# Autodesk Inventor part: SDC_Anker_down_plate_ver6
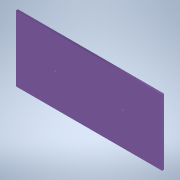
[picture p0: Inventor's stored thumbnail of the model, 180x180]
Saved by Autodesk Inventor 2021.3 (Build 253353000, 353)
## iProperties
Created: 2022-01
Part Number: SDC_Anker_down_plate_ver6
Material: アルミニウム 6061
Document SubType Name: Modeling
Designer: kengo
Density: 2.7 g/cm^3
Appearance: アルミニウム - フラット
Author: kengo
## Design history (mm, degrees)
sketch "スケッチ1"
  geometry: L1 (-589.671, 316.432)-(590.329, 316.432); L2 (590.329, 316.432)-(590.329, -283.568); L3 (590.329, -283.568)-(-589.671, -283.568); L4 (-589.671, -283.568)-(-589.671, 316.432); 1 further point
  constraints: 8 end point, 2 parallel, 1 horizontal, 1 perpendicular
  dimensions: "d0" = 600 distance of L3.end L1.start; "d1" = 1180 distance of L1.start L1.end
extrude "押し出し1" new body sketch "スケッチ1" distance "d2" = 15; taper "d3" = 0 deg
sketch "スケッチ4"
  geometry: L1 (-589.671, 316.432)-(-589.671, -283.568) reference; L2 (590.329, -283.568)-(590.329, 316.432) reference; L3 (-589.671, 261.432)-(590.329, 261.432); L4 (590.329, 261.432)-(590.329, -228.568); L5 (590.329, -228.568)-(-589.671, -228.568); L6 (-589.671, -228.568)-(-589.671, 261.432); L7 (590.329, 316.432)-(-589.671, 316.432) reference; L8 (-589.671, -283.568)-(590.329, -283.568) reference; L9 (-589.671, 316.432)-(590.329, 316.432); L10 (590.329, 316.432)-(590.329, -283.568); L11 (590.329, -283.568)-(-589.671, -283.568); L12 (-589.671, -283.568)-(-589.671, 316.432); 3 further points
  constraints: 16 end point, 4 parallel, 2 horizontal, 2 perpendicular, 2 point on line
  dimensions: "d58" = 490 distance between parallel lines of L5 L3; "d59" = 55 distance between parallel lines of L7 L3
extrude "押し出し2" cut sketch "スケッチ4" distance "d60" = 30; taper "d61" = 0 deg
sketch "スケッチ7" dims "d101" = 10, "d108" = 10
  geometry: L1 (590.329, 261.432)-(-589.671, 261.432) reference; L2 (-589.671, 261.432)-(-589.671, -228.568) reference; L3 (-589.671, 261.432)-(-589.671, -228.568); C1 r 3.324 at (-342.171, 138.932) reference; 5 further points
  constraints: 2 end point, 1 collinear, 1 horizontal, 1 vertical, 3 other
  dimensions: "d94" = 130 distance from line of L1 point (-204.671, 131.432); "d95" = 137.5 horizontal distance of point (-204.671, 131.432) C1.centre; "d98" = 500 distance of point (-204.671, 131.432) point (295.329, 131.432); "d105" = 230 distance of point (295.329, 131.432) point (295.329, -98.568)
hole "穴4" sketch "スケッチ7" diameter "d110" = 6.647; stored, may be unused: countersink angle "d114" = 90 deg, drill point angle "d116" = 118 deg; dims "d111" = 15, "d112" = 4, "d113" = 2, "d115" = 22.2
sketch "スケッチ8"
  geometry: L1 (-589.671, 261.432)-(590.329, 261.432) reference; L2 (590.329, -228.568)-(-589.671, -228.568) reference; L3 (-499.671, 261.432)-(-589.671, 261.432); L4 (-589.671, 261.432)-(-589.671, -228.568); L5 (-589.671, -228.568)-(-499.671, -228.568); L6 (-499.671, -228.568)-(-499.671, 261.432); 3 further points
  constraints: 8 end point, 2 parallel, 1 horizontal, 1 perpendicular, 1 point on line
  dimensions: "d119" = 90 distance between parallel lines of L4 L6
extrude "押し出し4" cut sketch "スケッチ8" distance "d120" = 20; taper "d121" = 0 deg
sketch "スケッチ9"
  geometry: L1 (590.329, 261.432)-(-499.671, 261.432) reference; L2 (590.329, -228.568)-(590.329, 261.432) reference; 2 further points
  dimensions: "d122" = 245 distance from line of L1 point (45.329, 16.432); "d123" = 545 distance from line of L2 point (45.329, 16.432)
hole "穴5" sketch "スケッチ9" at (45.329, 16.432) diameter "d124" = 8.376; stored, may be unused: countersink angle "d128" = 90 deg, drill point angle "d130" = 118 deg; dims "d125" = 15, "d126" = 4, "d127" = 2, "d129" = 51.2
sketch "スケッチ10"
  geometry: L1 (-499.671, -228.568)-(590.329, -228.568) reference; C1 r 3.324 at (-204.671, 131.432) reference; C2 r 3.324 at (295.329, 131.432) reference; 3 further points
  dimensions: "d131" = 0 horizontal distance of C1.centre point (-204.671, 16.432); "d132" = 245 distance from line of L1 point (-204.671, 16.432); "d133" = 245 distance from line of L1 point (295.329, 16.432); "d134" = 0 horizontal distance of C2.centre point (295.329, 16.432)
hole "穴6" sketch "スケッチ10" at (-204.671, 16.432), (295.329, 16.432) diameter "d135" = 18; stored, may be unused: countersink angle "d139" = 90 deg, drill point angle "d141" = 118 deg; dims "d136" = 6, "d137" = 4, "d138" = 2, "d140" = 22.2
node "ソリッド1"
